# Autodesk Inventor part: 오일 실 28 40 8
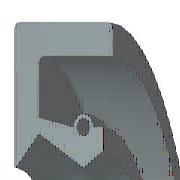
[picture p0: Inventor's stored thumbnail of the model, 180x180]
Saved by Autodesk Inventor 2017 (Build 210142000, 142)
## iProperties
IsCustomPart: 1
Created: 2012-02
Part Number: 오일 실 28 40 8
Material: 고무
Description: Oil-seal
Document SubType Name: Modeling
Standard: KS B 2804
Designer: mduedu
Standards Organization: KS
Language: en-US
Size Designation: D - 28 40 8
Categories: <MemberInstance><Categories><Category DisplayName="Shaft Parts" InternalName="7f7aeb1f-a693-4053-b835-cee3144e0d98" Mnemonic="SHFT"><Category DisplayName="Seali
Density: 0.93 g/cm^3
Mass: 2.83894 g
Surface Area: 40.7521 cm^2
Volume: 3.05262 cm^3
Appearance: 고무 - 검은색 - 버전 1.1
Author: mduedu
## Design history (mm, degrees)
sketch "Sketch1"
  geometry: L1 (0, 20)-(8, 20); L2 (8, 18.25)-(1.75, 18.25); L3 (1.75, 15.75)-(4.9, 14); L4 (4.9, 14)-(0, 14); L5 (0, 0)-(9.586, 0) reference; L6 (4.9, 14)-(6.3, 14.875); L7 (0, 18)-(0, -3) reference; L8 (-1.941, 0)-(11.507, 0) reference; L9 (4.2, 16.1)-(1.75, 16.71); L10 (1.75, 16.71)-(1.75, 18.25); L11 (0, 20)-(0, 14.088); L12 (4.9, 14)-(0, 14); L13 (1.75, 15.75)-(0.152, 14.028); L14 (8, 20)-(8, 18.25); L15 (5.6, 16.1)-(6.3, 16.1); L16 (6.3, 16.1)-(6.3, 14.875); C1 r 0.455 at (4.9, 16.1); A1 r 0.7 centre (4.9, 16.1) between (5.6, 16.1) and (4.2, 16.1); A2 r 0.088 centre (0.087, 14.088) between (0, 14.088) and (0.152, 14.028); 1 further point
  constraints: 28 end point, 5 horizontal alignment, 5 point on line, 4 point on circle, 4 vertical alignment, 3 centre point, 3 tangent, 2 collinear, 2 horizontal, 2 perpendicular, 1 coincident, 1 parallel
  dimensions: "d0" = 40 diameter of L1 L5 (= SD2); "d1" = 1.75 distance of L1.end L2.start (= SD); "d2" = 0.91 diameter of C1 (= SPDI); "d3" = 1.4 diameter of A1 (= SPDA); "d4" = 28 diameter of L3.end L5 (= NND); "d5" = 31.5 diameter of L3.start L5 (= TKDM); "d7" = 33.42 diameter of L9.end L5 (= TKDM + 0.24 x SWDT); "d8" = 1.75 distance between parallel lines of L11 L10 (= SD); "d9" = 4.9 distance from line of L11 C1.centre (= SPDST); "d10" = 32.2 diameter of C1.centre L5 (= HLDM); "d11" = 0.0875 radius of A2 (= 0.25 x LAB); "d12" = 6.3 distance between parallel lines of L11 L16 (= SDI); "d13" = 29.75 diameter of L6.end L5 (= ABDM); "d14" = 8 distance from line of L11 L1.end (= SWDT)
revolve "Body" stored, may be unused: angle "d17" = 90 deg
revolve "Spring1" stored, may be unused: angle "d18" = 90 deg
fillet "Fillet1" dims "d6" = 0.4 (= RR)
body "Solid1"
other parameters: "SD2" = 40 [user parameter; used in 1 equation term], "SWDT" = 8 [user parameter; used in 2 equation terms], "RR" = 0.4 [user parameter; used in 1 equation term], "SD" = 1.75 [user parameter; used in 2 equation terms], "NND" = 28 [user parameter; used in 1 equation term], "SPDA" = 1.4 [user parameter; used in 1 equation term], "SPDI" = 0.91 [user parameter; used in 1 equation term], "TKDM" = 31.5 [user parameter; used in 2 equation terms], "HLDM" = 32.2 [user parameter; used in 1 equation term], "ABDM" = 29.75 [user parameter; used in 1 equation term], "SDI" = 6.3 [user parameter; used in 1 equation term], "SPDST" = 4.9 [user parameter; used in 1 equation term], "LAB" = 0.35 [user parameter; used in 1 equation term], "d15" = 0, "d16" = 0, "d19" = 0
